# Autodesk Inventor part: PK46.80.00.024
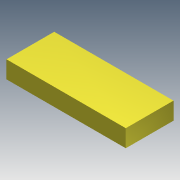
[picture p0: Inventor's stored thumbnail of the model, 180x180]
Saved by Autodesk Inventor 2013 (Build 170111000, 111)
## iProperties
Created: 2005-05
Part Number: PK46.80.00.024
Material: Steel, Mild
Document SubType Name: Modeling
Designer: salex
Manufacturer: Standard
Standards Organization: Custom
Density: 7.86 g/cm^3
Mass: 608.678 g
Surface Area: 146.08 cm^2
Volume: 77.44 cm^3
Author: salex
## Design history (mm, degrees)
sketch "Эскиз1"
  geometry: L1 (0, 0)-(110, 0); L2 (110, 0)-(110, 44); L3 (110, 44)-(0, 44); L4 (0, 44)-(0, 0)
  constraints: 8 end point, 2 parallel, 1 horizontal, 1 perpendicular, 1 other
  dimensions: "d0" = 110 distance of L1.start L1.end; "d1" = 44 distance of L3.end L1.start
extrude "Выдавливание1" new body sketch "Эскиз1" distance "d2" = 16; taper "d3" = 0 deg
body "Solid1"
